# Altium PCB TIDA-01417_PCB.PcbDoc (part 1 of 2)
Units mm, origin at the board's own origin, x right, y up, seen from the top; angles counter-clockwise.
Board outline 64 x 64 mm, 2 copper layers (Top Layer, Bottom Layer), stack 1.575 mm thick; 69 components, 44 nets, 174 pads, 84 vias.
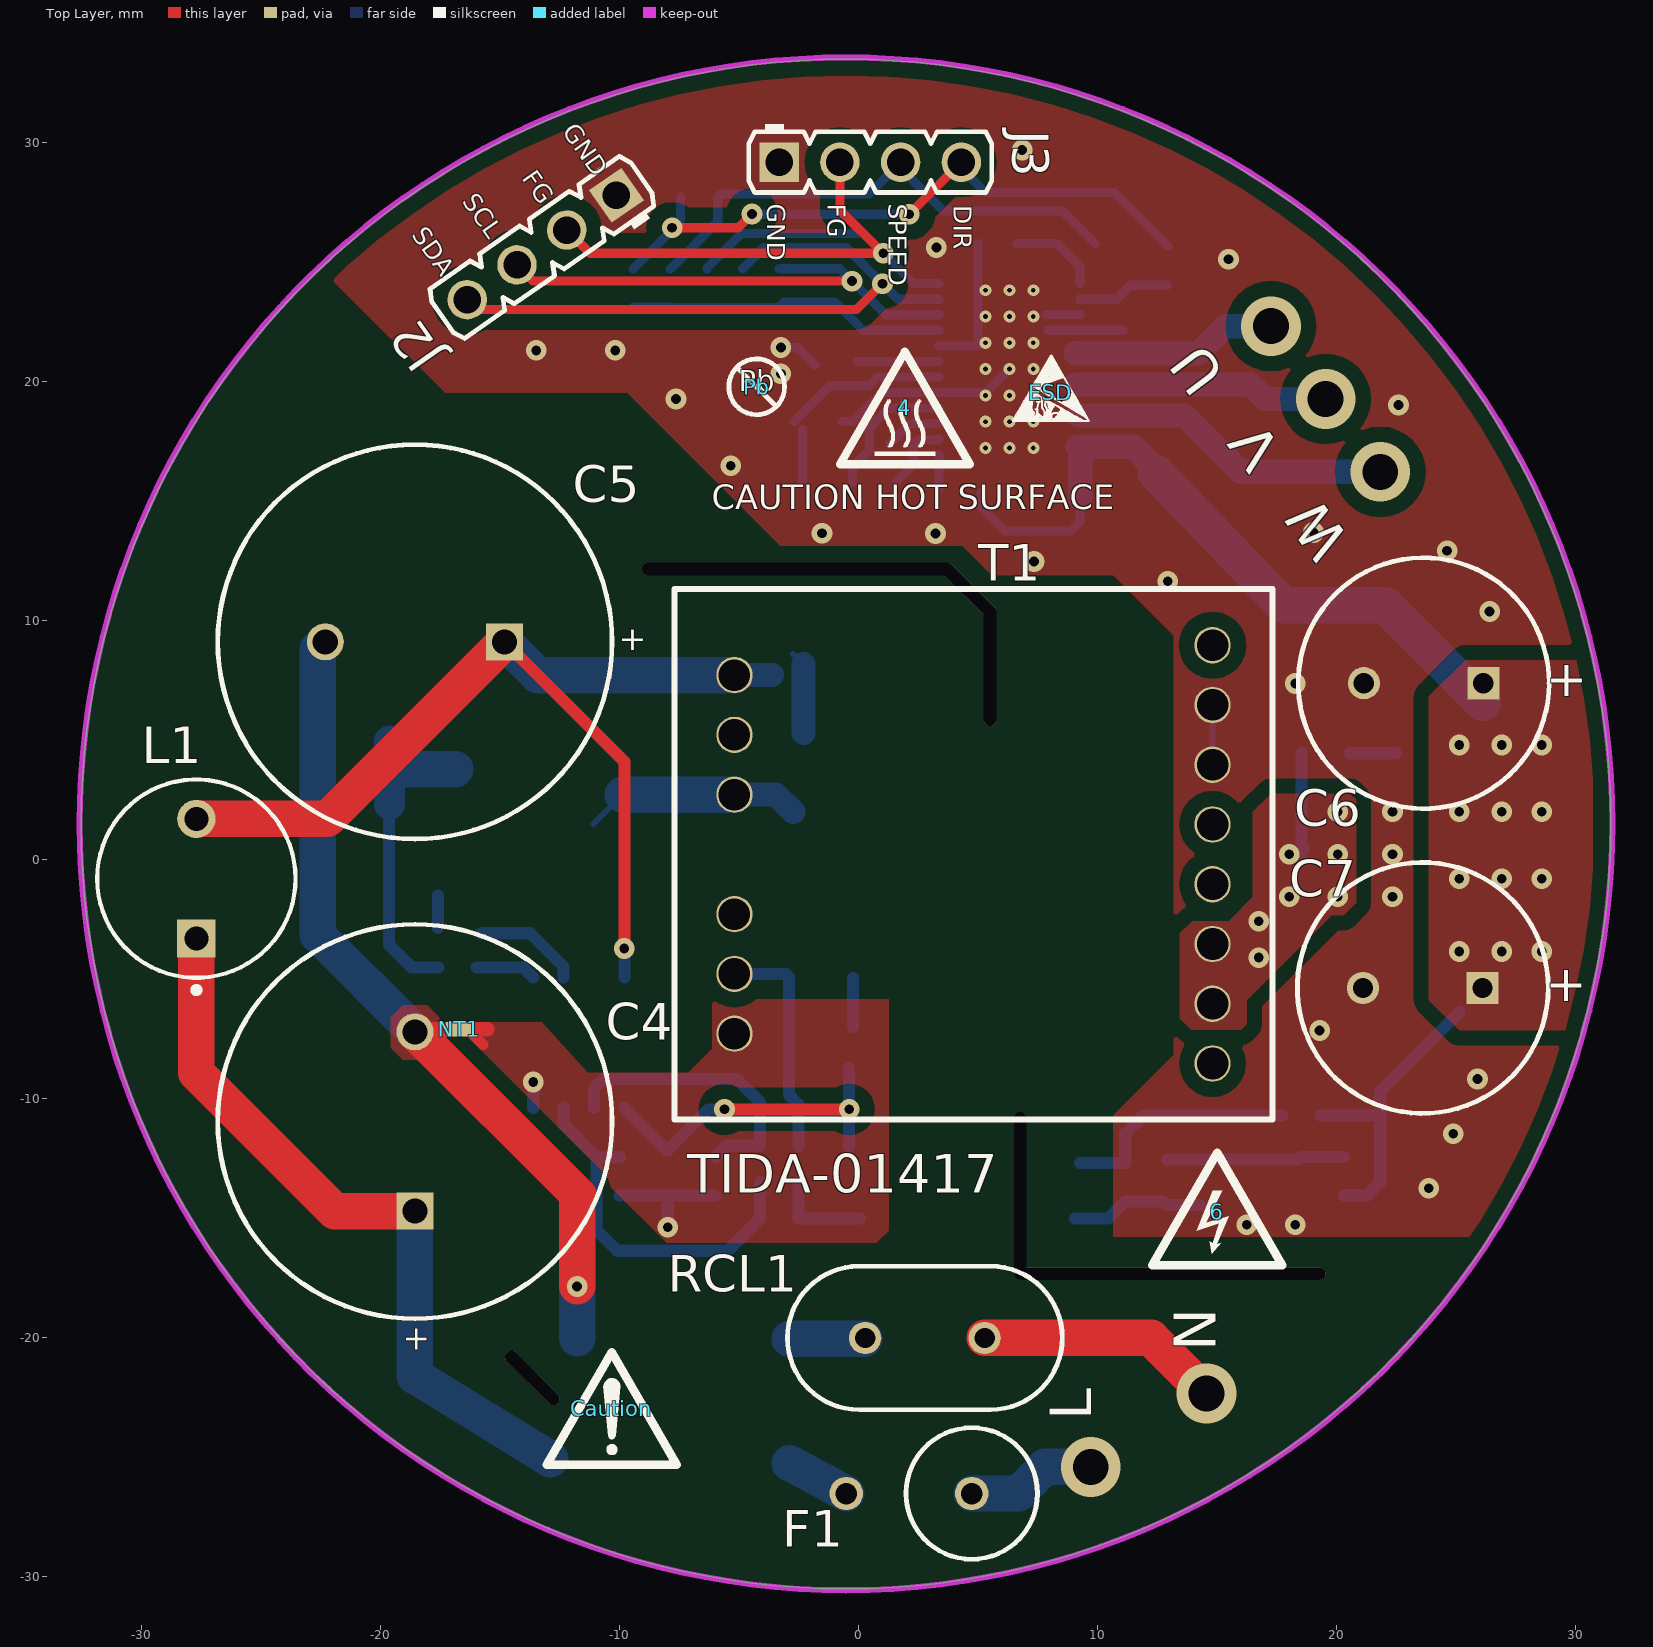
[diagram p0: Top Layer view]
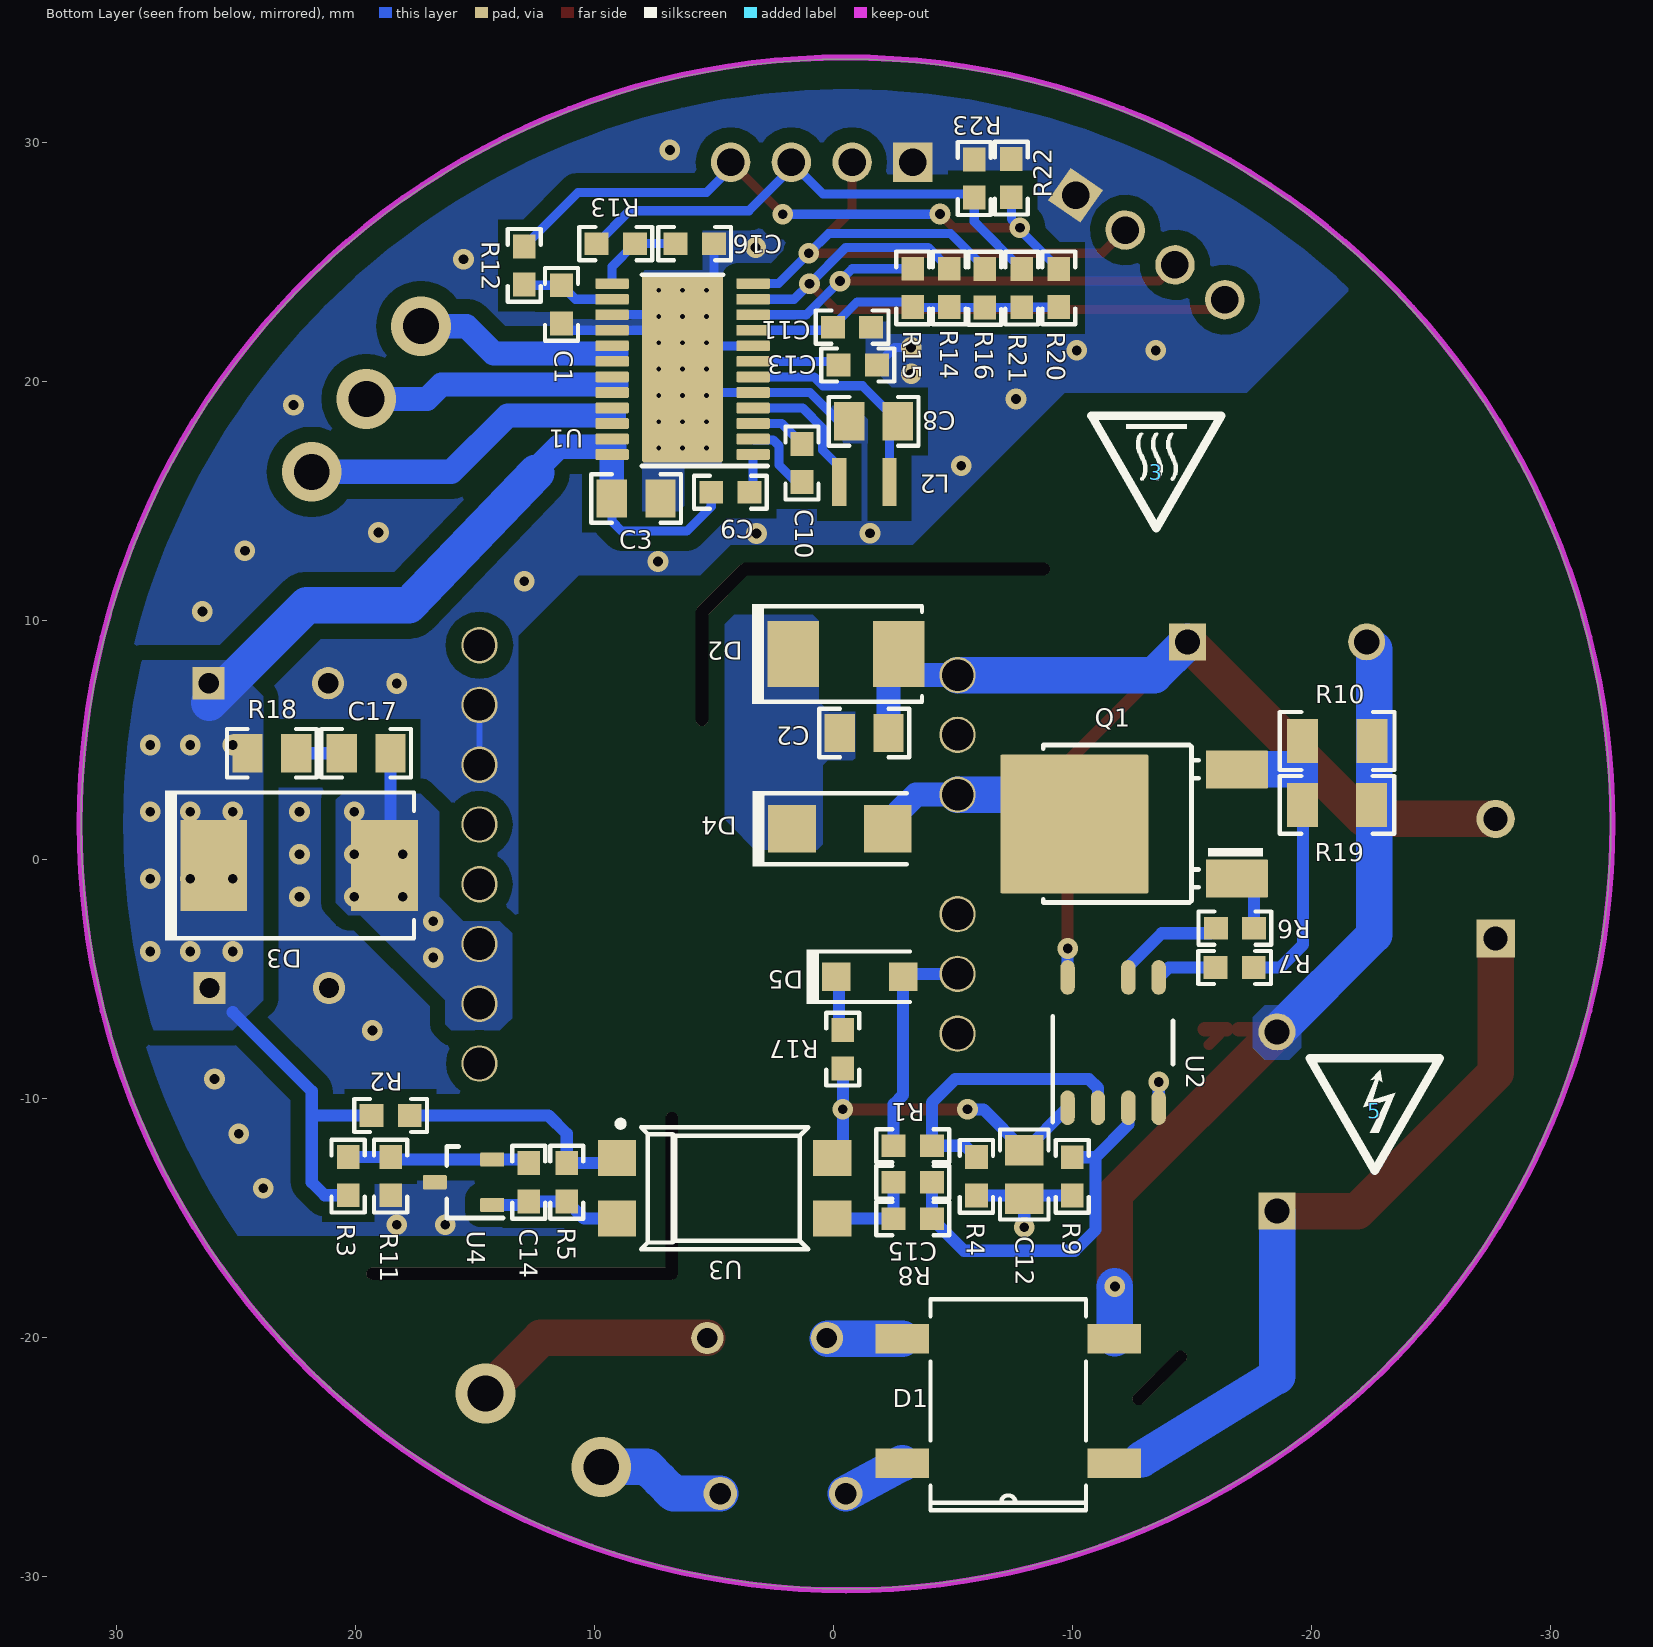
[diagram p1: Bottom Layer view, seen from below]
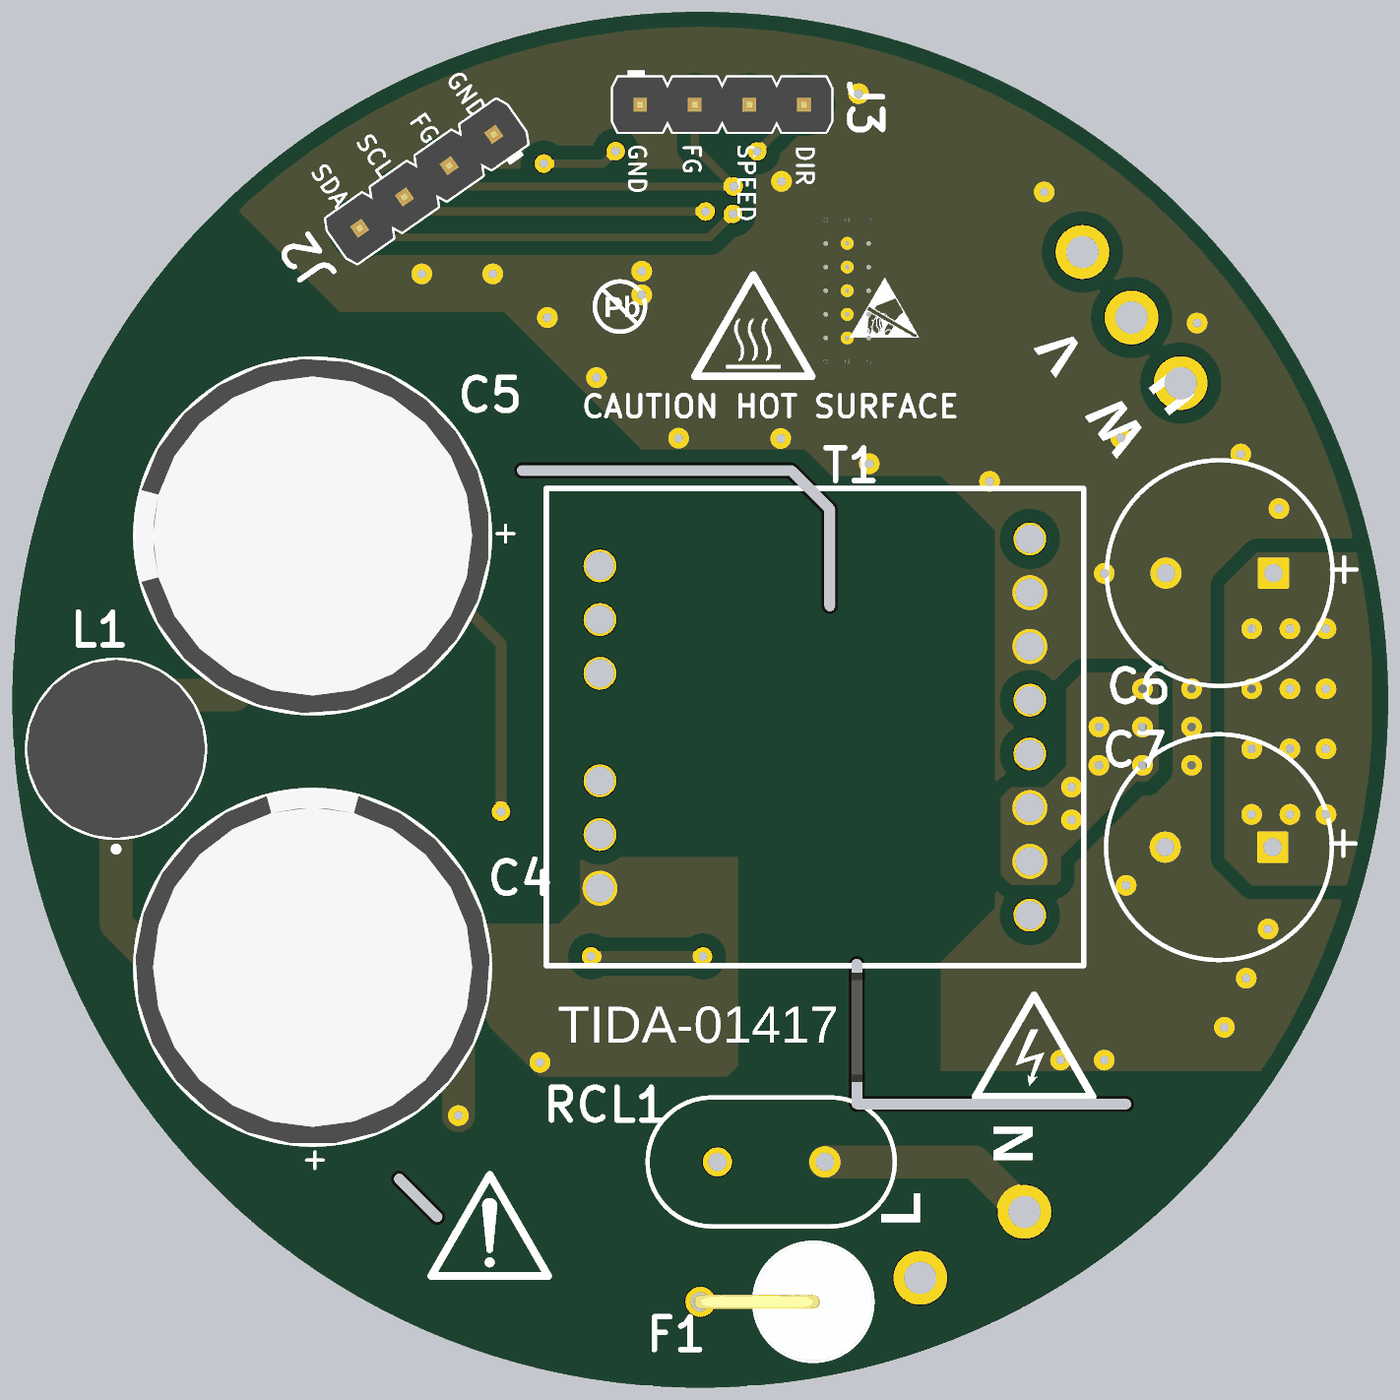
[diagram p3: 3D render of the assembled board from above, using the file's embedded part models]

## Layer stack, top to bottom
Top Solder: solder mask 0.0102, Solder Resist, Dk 3.5
Top Layer: signal copper 0.0356
Dielectric1: core 1.5037, FR-4, Dk 4.8
Bottom Layer: signal copper 0.0356
Bottom Solder: solder mask 0.0102, Solder Resist, Dk 3.5

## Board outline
-0.508,-30.514 cw(c-0.508,1.486) -32.508,1.486 cw(c-0.508,1.486) -0.508,33.486 cw(c-0.508,1.486) 31.492,1.486 cw(c-0.508,1.486)

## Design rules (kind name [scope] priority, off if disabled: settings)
AcuteAngle [All] p1: minimum=4.50000000000000E+0001 checktracksonly=FALSE
AssemblyTestPointUsage [All] p1: valid=2
BoardOutlineClearance BoardOutlineClearance_MountingHoles [OnCopper and InComponentClass('Mounting Holes')] p1: gap=1.016
BoardOutlineClearance BoardOutlineClearance_Poly [OnCopper and IsPoly] p2: gap=0.635
BoardOutlineClearance [OnCopper and Not InComponentClass('Logo') and not InComponentClass('FiducialMark') and not InRegion(1000,500,4000,800) and not InPoly] p3: gap=1.905
Clearance Clearance_Keepouts [((IsTrack Or IsArc) And Not InPoly) And IsFree and IsKeepOut vs ((IsTrack Or IsArc) And Not InPoly) And IsFree and IsKeepOut] p1: gap=0
Clearance Clearance_Poly [InPolygon] p2: gap=0.635
Clearance [All] p3: gap=0.2
ComponentClearance ComponentClearance_MountingHoles_FiducialMarks [InComponentClass('Mounting Holes') vs InComponentClass('FiducialMark')] p1: gap=1.27 collisioncheckmode=3 verticalgap=0.254 showdistances=FALSE
ComponentClearance ComponentClearance_Shunt [InComponentClass('Header') vs InComponentClass('Shunt')] p2: gap=0 collisioncheckmode=3 verticalgap=0 showdistances=FALSE
ComponentClearance ComponentClearance_Logo [InComponentClass('Logo')] p3: gap=1.27 collisioncheckmode=3 verticalgap=0.254 showdistances=FALSE
ComponentClearance ComponentClearance_ScrewToNut [(HasFootprint('NY PMS 440 0025 PH')) vs (HasFootprint('Keystone_1902C'))] p4: gap=0.127 collisioncheckmode=3 verticalgap=0.254 showdistances=FALSE
ComponentClearance ComponentClearance_MountingHoles [InComponentClass('Mounting Holes')] p5: gap=6.35 collisioncheckmode=3 verticalgap=2540 showdistances=FALSE
ComponentClearance ComponentClearance_SmallPassives [HasFootprint('0201*') or HasFootprint('0402*') or HasFootprint('0508') or HasFootprint('0603*') or HasFootprint('0612') or HasFootprint('0805*') or HasFootprint('0815*') or HasFootprint('0830*') or HasFootprint('1206*') or HasFootprint('1210*') or HasFootprint('1808*') or HasFootprint('1812*') or HasFootprint('1825*') or HasFootprint('2010*') or HasFootprint('2220*') or HasFootprint('2225*') or HasFootprint('2512*') or HasFootprint('2728*') or HasFootprint('3518*') vs HasFootprint('0201*') or HasFootprint('0402*') or HasFootprint('0508') or HasFootprint('0603*') or HasFootprint('0612') or HasFootprint('0805*') or HasFootprint('0815*') or HasFootprint('0830*') or HasFootprint('1206*') or HasFootprint('1210*') or HasFootprint('1808*') or HasFootprint('1812*') or HasFootprint('1825*') or HasFootprint('2010*') or HasFootprint('2220*') or HasFootprint('2225*') or HasFootprint('2512*') or HasFootprint('2728*') or HasFootprint('3518*')] p6: gap=0.38 collisioncheckmode=3 verticalgap=0.254 showdistances=FALSE
ComponentClearance ComponentClearance_THtoSMT [IsThruComponent vs IsSMTComponent] p7: gap=1.016 collisioncheckmode=3 verticalgap=0.762 showdistances=FALSE
ComponentClearance ComponentClearance_THtoTH [IsThruComponent vs IsThruComponent] p8: gap=0.762 collisioncheckmode=3 verticalgap=0.762 showdistances=FALSE
ComponentClearance [All] p9: gap=0.762 collisioncheckmode=3 verticalgap=0.254 showdistances=FALSE
DiffPairsRouting [All] p1: maxlimit=2.54 minlimit=0.254 mostfreqgap=0.254 toplayer_minwidth=0.381 toplayer_maxwidth=0.381 toplayer_prefwidth=0.381 bottomlayer_minwidth=0.381 bottomlayer_maxwidth=0.381 bottomlayer_prefwidth=0.381 maxuncoupledlength=25.4
FabricationTestPointUsage TestPointUsage [All] p1: valid=2 allowmultiple=FALSE
FabricationTestpoint Testpoint [All] p1: side=3 testpointundercomponent=TRUE minsize=1.016 maxsize=2.54 preferedsize=1.524 minholesize=0 maxholesize=1.016 preferedholesize=0.813 testpointgrid=0.025 allowsidetop=TRUE allowsidebottom=TRUE usegrid=TRUE gridtolerance=0
FanoutControl Fanout_LCC [IsLCC] p1: bgadir=Out bgaviamode=Centered fanoutstyle=Auto fanoutdirection=Alternating viagrid=0.025 // Fanout_LCC (Default Rule)
FanoutControl Fanout_BGA [IsBGA] p2: bgadir=Out bgaviamode=Centered fanoutstyle=Auto fanoutdirection=Alternating viagrid=0.025 // Fanout_BGA (Default Rule)
FanoutControl Fanout_Default [All] p4: bgadir=Out bgaviamode=Centered fanoutstyle=Auto fanoutdirection=Alternating viagrid=0.025 // Fanout_Default (Default Rule)
FanoutControl Fanout_Small [(CompPinCount < 5)] p5: bgadir=Out bgaviamode=Centered fanoutstyle=Auto fanoutdirection=OutThenIn viagrid=0.025 // Fanout_Small (Default Rule)
HoleSize [All] p1: absolutevalues=TRUE maxlimit=6.375 minlimit=0.2 maxpercent=80.000 minpercent=20.000
MinimumAnnularRing MinimumAnnularRing_ThermalPadVias [IsVia and InAnyComponent] p1: minimumring=0.15
MinimumAnnularRing [All] p2: minimumring=0.203
MinimumSolderMaskSliver MinimumSolderMaskSliver_Logo [InComponentClass('Logo') vs InComponentClass('Logo')] p1: minsoldermaskwidth=0.018
MinimumSolderMaskSliver [All] p2: minsoldermaskwidth=0.1
PlaneConnect [All] p1: planeconnectstyle=Relief reliefexpansion=0.254 reliefentries=4 reliefconductorwidth=0.254 reliefairgap=0.254
PolygonConnect [All] p1: connectstyle=Direct reliefconductorwidth=0.254 reliefentries=4 polygonreliefangle="90 Angle" airgapwidth=0.254
RoutingVias ThermalPadVias [IsVia and InAnyComponent] p1: holewidth=0.2 width=0.5 viastyle="Through Hole" minholewidth=0.2 minwidth=0.5 maxholewidth=0.33 maxwidth=0.6
RoutingVias [All] p2: holewidth=0.406 width=0.864 viastyle="Through Hole" minholewidth=0.2 minwidth=0.66 maxholewidth=1.016 maxwidth=1.651
SilkToBoardRegionClearance [Not ((IsComment or IsDesignator) And (Hide <> 'False')) and not InRegion(1000,500,4000,800)] p1:
SilkToSilkClearance SilkToSilkClearance_Pb-FreeLogo [(HasFootprint('Pb-Free_Overlay_Medium') OR HasFootprint('Pb-Free_Overlay_Small')) vs (HasFootprint('Pb-Free_Overlay_Medium') OR HasFootprint('Pb-Free_Overlay_Small'))] p1: silktosilkclearance=0
SilkToSilkClearance [All] p2: silktosilkclearance=0.102
SilkToSolderMaskClearance SilkToComponentPadClearance [IsPad and InAnycomponent] p1: minsilkscreentomaskgap=0.127 clearancetoexposedcopper=TRUE
SilkToSolderMaskClearance "Silk to Solder Mask Opening" [All] p2: minsilkscreentomaskgap=0.102 clearancetoexposedcopper=FALSE
SolderMaskExpansion [All] p1: expansion=0.05
Width [All] p1: maxlimit=2.54 minlimit=0.152 preferedwidth=0.254 checkconnectedcopper=TRUE
15 further rules are at their usual default settings.

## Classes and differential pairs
component class Header: J2 J3
component class AssemblyNote: ZZ1 ZZ2 ZZ3 ZZ4
component class TIDA-01417_BlankSheet: C1 C2 C3 C4 C5 C6 C7 C8 C9 C10 C11 C12 C13 C14 C15 C16 C17 D1 D2 D3 D4 D5 F1 J2 J3 L1 L2 NT1 Q1 R1 R2 R3 R4 R5 R6 R7 R8 R9 R10 R11 R12 R13 R14 R15 R16 R17 R18 R19 R20 R21 R22 R23 RCL1 T1 U1 U2 U3 U4
component class TIDA-01417_EVM_Hardware: 3 4 5 6 !PCB Caution ESD Pb ZZ1 ZZ2 ZZ3 ZZ4

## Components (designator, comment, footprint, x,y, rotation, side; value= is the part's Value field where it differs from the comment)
3 "CAUTION HOT SURFACE" IEC_HotSurface_small -13.496,16.2 r0 bottom
4 "CAUTION HOT SURFACE" IEC_HotSurface_small 1.96,18.896 r0 top
5 "HIGH VOLTAGE" IEC_HighVoltage_small -22.627,-10.539 r0 bottom
6 "HIGH VOLTAGE" IEC_HighVoltage_small 15.022,-14.742 r0 top
C1 "CGA3E2X7R2A102K080AA" 0603 11.394,23.225 r90 bottom
C2 "C0805C102JBRACTU" 0805_HV#1 -1.27,5.296 r0 bottom
C3 "C2012X5R1V106K085AC" 0805_HV#1 8.271,15.106 r0 bottom
C4 "ESMG451ELL470MLP1S" SMG_1600x3550 -18.542,-10.96 r90 top
C5 "ESMG451ELL470MLP1S" SMG_1600x3550 -18.542,9.106 r180 top
C6 "ELXZ350ELL471MJ20S" Chemi-Con_1000x2000 23.658,7.377 r180 top
C7 "ELXZ350ELL471MJ20S" Chemi-Con_1000x2000 23.622,-5.372 r180 top
C8 "C2012X5R1V106K085AC" 0805_HV#1 -1.663,18.331 r180 bottom
C9 "C1608X5R1H104K080AA" 0603 4.328,15.363 r0 bottom
C10 "C1608X5R1H104K080AA" 0603 1.333,16.587 r90 bottom
C11 "C1608X5R1H105K080AB" 0603 -0.762,22.273 r0 bottom
C12 "C2012X5R1V106K085AC" 0805_HV#1 -7.965,-13.176 r90 bottom
C13 "C1608X5R1H105K080AB" 0603 -1,20.685 r0 bottom
C14 "GRM188R71H561KA01D" 0603 12.764,-13.5 r270 bottom
C15 "C1608X5R1H473K080AA" 0603 -3.302,-13.5 r0 bottom
C16 "CGA3E2X7R2A102K080AA" 0603 5.821,25.765 r0 bottom
C17 "C0805C102JBRACTU" 0805_HV#1 19.565,4.445 r0 bottom
Caution "CAUTION.  READ USER GUIDE BEFORE USE" IEC_Caution_small -10.303,-22.96 r0 top
D1 "DF1506S-T" DF-S -7.296,-22.652 r0 bottom
D2 "SMBJ170A-13-F" SMB -0.508,8.598 r180 bottom
D3 "MBRS4201T3G" SMC 22.37,-0.248 r180 bottom
D4 "US1M-13-F" SMA -0.254,1.284 r180 bottom
D5 "PMEG10010ELRX" SOD-123W -1.505,-4.904 r180 bottom
ESD "ESD Susceptible" ESD_Overlay_small 8.045,19.556 r0 top
F1 "048712.5MXEP" Fuse_217_015_Verical 4.752,-26.523 r0 top
J2 "61300411121" WURTH_61300411121#1 -13.208,25.87 r225 top
J3 "61300411121" WURTH_61300411121#2 0.508,29.172 r0 top
L1 "768772102" WE-TI_8095 -27.686,-0.8 r90 top
L2 "CB2518T470K" IND_CB2518 -1.28,15.789 r180 bottom
NT1 "Net-Tie" Net-Tie_10mil -16.681,-7.104 r180 top net-tie
Pb "Pb-Free Symbol" Pb-Free_Overlay_Small -4.244,19.777 r0 top
Q1 "SPD04N80C3" DPAK -13.462,1.486 r0 bottom
R1 "RC0603FR-0775KL" 0603 -3.302,-11.976 r0 bottom
R2 "RC0603FR-071K5L" 0603 18.542,-10.706 r0 bottom
R3 "RT0603BRD07383KL" 0603 20.32,-13.246 r270 bottom
R4 "RC0603JR-0724KL" 0603 -5.964,-13.253 r90 bottom
R5 "RC0603FR-071KL" 0603 11.176,-13.5 r90 bottom
R6 "MCR03EZPJ000" 0603 -16.78,-2.872 r180 bottom
R7 "RC0603JR-072K7L" 0603 -16.765,-4.515 r180 bottom
R8 "RC0603FR-07100KL" 0603 -3.302,-15.024 r180 bottom
R9 "RC0603FR-0722KL" 0603 -9.974,-13.254 r90 bottom
R10 "ERJ-8RQFR43V" 1206 -21.056,4.957 r0 bottom
R11 "RC0603FR-0744K2L" 0603 18.542,-13.246 r90 bottom
R12 "RC0603FR-07100RL" 0603 12.954,24.854 r270 bottom
R13 "RC0603FR-07100RL" 0603 9.123,25.765 r180 bottom
R14 "RC0603JR-075K1L" 0603 -4.826,23.914 r90 bottom
R15 "RC0603JR-075K1L" 0603 -3.302,23.914 r90 bottom
R16 "RC0603JR-075K1L" 0603 -6.317,23.898 r90 bottom
R17 "CRCW060310R0JNEA" 0603 -0.375,-7.935 r90 bottom
R18 "RC0805JR-0710RL" 0805_HV#2 23.513,4.447 r180 bottom
R19 "NC" 1206 -21.049,2.284 r0 bottom
R20 "RC0603JR-075K1L" 0603 -9.406,23.912 r270 bottom
R21 "RC0603JR-075K1L" 0603 -7.863,23.902 r270 bottom
R22 "RC0603JR-075K1L" 0603 -7.424,28.505 r270 bottom
R23 "RC0603JR-075K1L" 0603 -5.875,28.49 r270 bottom
RCL1 "B57236S479M" THERM_B57236S0 2.792,-20.016 r180 top
T1 "Used in BOM report" PCBComponent_1 4.826,0.216 r0 top
U1 "DRV10983PWP" PWP0024B_N 6.329,20.515 r0 bottom
U2 "UCC28740DR" D0007A_N -11.684,-7.658 r90 bottom
U3 "LTV-817S" DIP254P762X350-4 4.572,-13.754 r180 bottom
U4 "TL431BQDBZT" DBZ0003A_N 15.494,-13.5 r0 bottom
ZZ1 "This Assembly Note is for PCB labels only" AssemblyNoteLabel -45.593,61.125 r0 top
ZZ2 "These assemblies are ESD sensitive, ESD precautions shall be observed." AssemblyNote -45.593,58.359 r0 top
ZZ3 "These assemblies must be clean and free from flux and all contaminants. Use of no clean flux is not acceptable." AssemblyNote -45.593,56.11 r0 top
ZZ4 "These assemblies must comply with workmanship standards IPC-A-610 Class 2, unless otherwise specified." AssemblyNote -45.593,53.861 r0 top

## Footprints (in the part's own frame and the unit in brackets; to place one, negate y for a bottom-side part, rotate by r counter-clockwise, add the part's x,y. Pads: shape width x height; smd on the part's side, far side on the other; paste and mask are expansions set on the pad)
0603 [mm] "0603 from SM-752 data"
  rect 1x0.95 smd: 1(-0.8,0) 2(0.8,0)
  silkscreen extent -1.52,-0.69 1.52,0.69, body extent -0.87,-0.47 0.87,0.47, height 1
0805_HV#1 [mil] "0805 with 30mil clearance between pads"
  rect 50x63 smd: 1(-40,0) 2(40,0)
  silkscreen extent -74,-40 74,40, body extent -43,-29 43,29, height 57
0805_HV#2 [mil] "0805 with 30mil clearance between pads"
  rect 50x63 smd: 1(40,0) 2(-40,0)
  silkscreen extent -74,-40 74,40, body extent -43,-29 43,29, height 57
1206 [mm] "1206 from SM-752 data"
  rect 1.3x1.85 smd: 1(-1.45,0) 2(1.45,0)
  silkscreen extent -2.4,-1.21 2.4,1.21, body extent -1.7,-0.9 1.7,0.9, height 1.35
AssemblyNote [mm] "Assembly Note"
AssemblyNoteLabel [mm] "Assembly Note for PCB Labels"
Chemi-Con_1000x2000 [mm] "TH, 2-Leads, Body 10x20mm, Pin Spacing 5mm"
  rect 1.35x1.35 hole 0.85: 1(-2.5,0)
  round 1.35 hole 0.85: 2(2.5,0)
  silkscreen extent -5.25,-5.25 5.25,5.25, body extent -5.25,-5.25 5.25,5.25, height 21.5
D0007A_N [mm] "SOIC, 7-Leads, Body 4.9x3.9mm, Pitch 1.27mm, IPC Medium Density"
  oval 1.45x0.6 smd: 1(-2.725,1.905) 2(-2.725,0.635) 3(-2.725,-0.635) 4(-2.725,-1.905) 5(2.725,-1.905) 6(2.725,-0.635) 8(2.725,1.905)
  silkscreen extent -3.32,-2.5 1.1,2.52, body extent -3.01,-2.45 3.01,2.45, height 1.75
DBZ0003A_N [mm] "SOT23, 3-Leads, Body 2.9x1.3mm, Pitch 0.95mm, Lead Span 2.4mm, IPC Medium Density"
  rrect17% 1x0.6 smd: 1(-1.2,0.95) 2(-1.2,-0.95) 3(1.2,0)
  silkscreen extent -1.65,-1.5 0.7,1.5, body extent -1.26,-1.46 1.26,1.46, height 0.98
DF-S [mil] "Diodes Inc. recommended land pattern per ap02001.pdf rev 30"
  rect 88x49 smd: 1(-174.5,102.36) 2(-174.5,-102.36) 3(174.5,-102.36) 4(174.5,102.36)
  silkscreen extent -128,-168 128,180, body extent -205,-168 205,168, height 108
DIP254P762X350-4 [mm] "LITE-ON"
  rect 1.6x1.5 smd: 1(-4.5,1.27) 2(-4.5,-1.27) 3(4.5,-1.27) 4(4.5,1.27)
  silkscreen extent -4.47,-2.55 3.5,2.82, body extent -5.23,-2.55 5.23,2.55, height 4.62
DPAK [mm] "D-PAK, 3-Pads, Body 6.22x6.73mm (max), TO-252AA using nominal STEP model"
  rrect6% 2.6x1.6 smd: 1(-3.4,2.28) 3(-3.4,-2.28)
  rrect2% 6.2x5.8 smd paste-2.9: 4(3.4,0)
  silkscreen extent -4.5,-3.3 4.7,3.28, body extent -3.86,-3.29 5.84,3.29, height 2.48
ESD_Overlay_small [mm]
  silkscreen extent -1.58,-1.23 1.62,1.55
Fuse_217_015_Verical [mm] "TH, 2-Leads, Dia 5.5mm, Vertical, Pin Spacing 5.25mm"
  round 1.4 hole 0.9: 1(0,0) 2(-5.25,0)
  silkscreen extent -2.75,-2.75 2.75,2.75, body extent -5.57,-2.74 2.75,2.75, height 23.82
IEC_Caution_small [mm]
  silkscreen extent -2.72,-2.36 2.72,2.35
IEC_HighVoltage_small [mm]
  silkscreen extent -2.72,-2.24 2.72,2.47
IEC_HotSurface_small [mm]
  silkscreen extent -2.72,-2.36 2.72,2.35
IND_CB2518 [mm] "TAIYO YUDEN"
  rect 0.6x2 smd: 1(-1.05,0) 2(1.05,0)
  body extent -1.35,-1 1.35,1, height 2
Net-Tie_10mil [mm] "10mil net tie, no solder mask opening, no solder paste"
  rect 0.6x0.6 smd paste-0.127 mask-0.127: 1(-0.254,0) 2(0.254,0)
  Top Layer region: -0.152,0.127 0.152,0.127 0.152,-0.127 -0.152,-0.127
Pb-Free_Overlay_Small [mm]
  silkscreen extent -1.16,-1.17 1.17,1.17
PCBComponent_1 [mm]
  round 1.524 hole 1.32: 1(-10,7.5) 2(-10,5) 3(-10,2.5) 4(-10,-2.5) 5(-10,-5) 6(-10,-7.5) 7(10,-8.75) 8(10,-6.25) 9(10,-3.75) 10(10,-1.25) 11(10,1.25) 12(10,3.75) 13(10,6.25) 14(10,8.75)
  silkscreen extent -12.5,-11.1 12.5,11.1
PWP0024B_N [mm] "TSOP, 24-Leads, Body 7.9x4.5mm (max), Pitch 0.65mm, IPC Medium Density"
  rrect22% 1.4x0.45 smd: 1(-2.95,3.575) 2(-2.95,2.925) 3(-2.95,2.275) 4(-2.95,1.625) 5(-2.95,0.975) 6(-2.95,0.325) 7(-2.95,-0.325) 8(-2.95,-0.975) 9(-2.95,-1.625) 10(-2.95,-2.275) 11(-2.95,-2.925) 12(-2.95,-3.575) 13(2.95,-3.575) 14(2.95,-2.925) 15(2.95,-2.275) 16(2.95,-1.625) 17(2.95,-0.975) 18(2.95,-0.325) 19(2.95,0.325) 20(2.95,0.975) 21(2.95,1.625) 22(2.95,2.275) 23(2.95,2.925) 24(2.95,3.575)
  rrect6% 3.4x7.8 smd paste-2 mask-2: 25(0,0)
  rrect4% 2.4x5.16 on Bottom Paste: 25(0,0)
  rrect4% 2.4x5.16 on Bottom Solder: 25(0,0)
  silkscreen extent -3.55,-3.95 1.7,4.05, body extent -3.21,-3.9 3.21,3.9, height 1.2
SMA [mm] "Molded Diode, 2-Leads, Body 4.3x2.6mm, IPC Medium Density, based on OnSemi component dimensions and land pattern"
  rect 2x2 smd: 1(-2,0) 2(2,0)
  silkscreen extent -3.66,-1.57 2.79,1.57, body extent -2.6,-1.3 2.6,1.3, height 2.42
SMB [mm] "Molded Diode, 2-Leads, Body 5.4x3.6mm, IPC Medium Density, based on OnSemi component dimensions"
  rect 2.159x2.743 smd: 1(-2.21,0) 2(2.21,0)
  silkscreen extent -3.94,-2.08 3.18,2.08, body extent -2.7,-1.8 2.7,1.8, height 2.32
SMC [mil] "Molded Diode, 2-Leads, Body 6.9x5.8mm, IPC Medium Density, based on OnSemi component dimensions and land patterns"
  rect 110x150 smd: 1(-140.49,0) 2(140.49,0)
  silkscreen extent -221,-123 189,124, body extent -156,-116 157,116, height 91
SMG_1600x3550 [mm] "TH, 2-Leads, Dia 16mm, Pin Spacing 7.5mm"
  rect 1.55x1.55 hole 1.05: 1(-3.75,0)
  round 1.55 hole 1.05: 2(3.75,0)
  silkscreen extent -8.25,-8.25 8.25,8.25, body extent -8.25,-8.25 8.26,8.25, height 37.01
SOD-123W [mm] "NXP recommended land pattern"
  rect 1.2x1.2 smd paste-0.05: 1(-1.4,0) 2(1.4,0)
  silkscreen extent -2.64,-1.14 1.68,1.14, body extent -1.85,-0.95 1.85,0.95, height 1.1
THERM_B57236S0 [mm] "EPCOS"
  round 1.35 hole 0.85: 1(-2.5,0) 2(2.5,0)
  silkscreen extent -5.75,-3 5.75,3, body extent -5.75,-3 5.7,3, height 15.99
WE-TI_8095 [mm] "Wurth WE-TI 8095"
  rect 1.6x1.6 hole 1: 1(-2.5,0)
  round 1.6 hole 1: 2(2.5,0)
  silkscreen extent -4.79,-4.15 4.15,4.15, body extent -4.12,-4.14 4.15,4.14, height 10
WURTH_61300411121#1 [mm] "Header, 2.54mm, 4x1, TH"
  rect 1.65x1.65 hole 1.15 rot 170: 1(-3.549,0.832)
  round 1.65 hole 1.15: 2(-1.047,0.391) 3(1.454,-0.05) 4(3.956,-0.491)
  silkscreen extent -4.93,-1.92 5.34,2.51, body extent -5.02,-1.96 5.43,2.3, height 8.54
WURTH_61300411121#2 [mm] "Header, 2.54mm, 4x1, TH"
  rect 1.65x1.65 hole 1.15: 1(-3.81,0)
  round 1.65 hole 1.15: 2(-1.27,0) 3(1.27,0) 4(3.81,0)
  silkscreen extent -5.08,-1.27 5.08,1.6, body extent -5.08,-1.27 5.08,1.27, height 8.54

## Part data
3 4: library part IEC_HotSurface, "IEC 61010-1 Hot Surface Warning"
5 6: library part IEC_HighVoltage, "IEC 61010-1 High Voltage Warning"
C1 C16: "CAP, CERM, 1000 pF, 100 V, +/- 10%, X7R, AEC-Q200 Grade 1, 0603"
C2 C17: "CAP, CERM, 1000 pF, 630 V, +/- 5%, X7R, 0805"
C3 C8 C12: "CAP, CERM, 10 µF, 35 V, +/- 10%, X5R, 0805"
C4 C5: "CAP, AL, 47 µF, 450 V, +/- 20%, TH"
C6 C7: "CAP, AL, 470 µF, 35 V, +/- 20%, AEC-Q200 Grade 2, TH"
C9 C10: "CAP, CERM, 0.1 µF, 50 V, +/- 10%, X5R, 0603"
C11 C13: "CAP, CERM, 1 µF, 50 V, +/- 10%, X5R, 0603"
C14: "CAP, CERM, 560 pF, 50 V, +/- 10%, X7R, 0603"
C15: "CAP, CERM, 0.047 µF, 50 V, +/- 10%, X5R, 0603"
Caution: library part IEC_Caution, "IEC 61010-1 Caution Warning"
D1: "Diode, Switching-Bridge, 600 V, 1.5 A, DF-S"
D2: "Diode, TVS, Uni, 170 V, 275 Vc, SMB"
D3: "Diode, Schottky, 200 V, 4 A, SMC"
D4: "Diode, Ultrafast, 1000 V, 1 A, SMA"
D5: "Diode, Schottky, 100 V, 1 A, AEC-Q101, SOD-123W"
ESD: library part ESD_Susceptible, "ESD Susceptible Symbol"
F1: library part 0217015.MXEP, "FUSE 420VAC/DC 5X20 FA PT 12.5A"
J2 J3: "Header, 2.54 mm, 4x1, Gold, TH"
L1: "Inductor, Shielded Drum Core, Metal Composite, 1 mH, 0.5 A, 1.7 ohm, TH"
L2: "Inductor, Wirewound, Ferrite, 47 µH, 0.11 A, 1.235 ohm, SMD"
NT1: "Single point connection between nets."
Pb: library part Pb-Free
Q1: "MOSFET, N-CH, 800 V, 4 A, DPAK"
R1: "RES, 75.0 k, 1%, 0.1 W, 0603"
R2: "RES, 1.50 k, 1%, 0.1 W, 0603"
R3: "RES, 383 k, 0.1%, 0.1 W, 0603"
R4: "RES, 24 k, 5%, 0.1 W, 0603"
R5: "RES, 1.00 k, 1%, 0.1 W, 0603"
R6: "RES, 0, 5%, 0.1 W, 0603"
R7: "RES, 2.7 k, 5%, 0.1 W, 0603"
R8: "RES, 100 k, 1%, 0.1 W, 0603"
R9: "RES, 22.0 k, 1%, 0.1 W, 0603"
R10: "RES, 0.43, 1%, 0.25 W, AEC-Q200 Grade 1, 1206"
R11: "RES, 44.2 k, 1%, 0.1 W, 0603"
R12 R13: "RES, 100, 1%, 0.1 W, 0603"
R14 R15 R16 R20 R21 R22 R23: "RES, 5.1 k, 5%, 0.1 W, 0603"
R17: "RES, 10, 5%, 0.1 W, 0603"
R18: "RES, 10, 5%, 0.125 W, 0805"
R19: library part ERJ-8RQFR82V, "RES, 0.82, 1%, 0.25 W, 1206"
RCL1: library part B57236S0100M000, "ICL 4.7 OHM 20% 4.6A 11.51MM"
T1: library part 36W24V
U1: "12- to 24-V, Three-Phase, Sensorless BLDC Motor Driver, PWP0024B (TSSOP-24)"
U2: "Constant-Voltage, Constant-Current Flyback Controller Using Opto-Coupler Feedback, D0007A (SOIC-7)"
U3: "Optocoupler, 5 kV, 50-600% CTR, SMT"
U4: "Adjustable Precision Shunt Regulator, 34 ppm / degC, 100 mA, -40 to 125 degC, 3-pin SOT-23 (DBZ), Green (RoHS & no Sb/Br)"
ZZ1: library part AssemblyNoteLabel
ZZ2 ZZ3 ZZ4: library part AssemblyNote

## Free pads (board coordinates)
  oval 0.508x3 hole 0.508 slot 3 at 135 deg unplated rot 45 mask+0.127: 0(-13.629,-21.686) 0(4.615,11.258)
  oval 13x0.508 hole 0.508 slot 13 at 0 deg unplated mask+0.127: 0(-2.54,12.154) 0(13.05,-17.324)
  oval 0.508x5 hole 0.508 slot 5 at 90 deg unplated mask+0.127: 0(5.516,8.097)
  oval 0.508x7 hole 0.508 slot 7 at 90 deg unplated mask+0.127: 0(6.777,-14.062)

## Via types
v1: diameter 0.864, hole 0.406, Top Layer to Bottom Layer, 58 vias
v2: diameter 0.5, hole 0.2, Top Layer to Bottom Layer, 15 vias
v3: diameter 0.5, hole 0.2, Top Layer to Bottom Layer, tented both sides, 6 vias
v4: diameter 2.5, hole 1.5, Top Layer to Bottom Layer, 5 vias

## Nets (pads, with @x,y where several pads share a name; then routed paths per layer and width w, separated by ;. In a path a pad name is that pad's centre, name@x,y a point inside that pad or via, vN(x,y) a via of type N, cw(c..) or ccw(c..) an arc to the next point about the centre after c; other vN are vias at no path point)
+3.3V: C11.2 R14.1 R15.1 R16.1 R20.2 R21.2 U1.9 | length 13
  Bottom Layer w0.381: R20.2@-9.397,23.102 R21.2@-7.863,23.102 -7.859,23.098 R16.1@-6.317,23.098 R15.1@-3.318,23.098 ; R15.1@-3.237,23.179 -3.086,23.33 -0.978,23.33 C11.2@0.038,22.314 ; C11.2@0.211,22.14 U1.9@3.38,22.14
+24V: C3.2 C6.1 C7.1 C9.2 D3.1 R2.2 R3.2 R18.2 U1.23 U1.24 | length 42.6
  Bottom Layer w0.381: C9.2@5.128,15.363 5.128,14.763 6.153,13.738 8.867,13.738 9.28,14.151 C3.2@9.28,15.098
  Bottom Layer w0.508: R2.2@19.342,-10.706 21.844,-10.706 ; R3.2@20.32,-14.046 21.298,-14.046 21.844,-13.5 21.844,-10.706 ; 25.146,-6.388 21.844,-9.69 21.844,-10.706
  Bottom Layer w1.016: 9.175,17.265 11.512,17.265 12.445,16.332 12.445,16.187 ; C3.2@9.287,15.106 U1.24@9.287,17.154
  Bottom Layer w1.524: 12.445,16.187 17.78,10.63 22.058,10.63 26.122,6.566
  other v1: 25.146,-3.848 26.924,-3.848 28.602,-3.848 25.146,-0.8 26.924,-0.8 28.602,-0.8 25.146,1.994 26.924,1.994 28.602,1.994 25.146,4.788 26.924,4.788 28.602,4.788
DIR: J3.4 R12.1 R20.1 R22.2 | length 27
  Top Layer w0.381: v1(-7.783,26.43) -5.017,26.43 v1(-4.439,27.008) ; v1(2.14,26.994) J3.4@4.318,29.172
  Bottom Layer w0.381: R20.1@-9.406,24.712 v1@-7.736,26.383 ; v1(-7.783,26.43) -7.424,26.79 R22.2@-7.424,27.705 ; v1(-4.439,27.008) -4.439,26.994 v1(2.14,26.994) ; J3.4@4.318,28.918 5.334,27.902 10.706,27.902 R12.1@12.954,25.654
FG: J2.2 J3.2 R16.2 U1.12 | length 29.4
  Top Layer w0.381: J2.2@-12.191,26.334 -11.219,25.362 v1(1.048,25.362) -0.762,27.172 J3.2@-0.762,29.172
  Bottom Layer w0.381: R16.2@-6.317,24.698 -6.317,24.751 -4.882,26.186 0.224,26.186 v1(1.048,25.362) 2.32,24.09 U1.12@3.38,24.09
GND: C1.1 C3.1 C6.2 C7.2 C8.1 C11.1 C13.1 C16.1 J2.1 J3.1 R11.1 R22.1 R23.1 T1.12 T1.13 U1.5 U1.8 U1.15 U1.16 U1.25@6.329,20.515 U4.3 | length 22.3
  Bottom Layer w0.254: T1.12@14.826,3.966 T1.13@14.826,6.466
  Bottom Layer w0.381: v1@-3.205,21.421 -2.536,21.421 -2.341,21.226 C13.1@-1.8,20.685 ; C8.1@-0.647,18.331 -0.205,18.331 1.004,19.54 U1.5@3.38,19.54 5.355,19.54 v2(6.329,20.515) ; U1.8@3.38,21.49 U1.25@5.021,21.49 ; U1.25@5.021,21.823 C16.1@5.021,25.765 ; U1.25@7.853,22.801 U1.15@9.28,22.79 ; U1.25@7.955,22.14 U1.16@9.28,22.14 C1.1@11.109,22.14
  other v1: 16.256,-15.278 18.288,-15.278 23.876,-13.754 24.892,-11.468 25.908,-9.182 19.304,-7.15 22.352,-1.562 22.352,0.216 22.352,1.994 18.288,7.366 26.416,10.376 12.954,11.646 7.356,12.467 24.638,12.916 3.234,13.639 -1.515,13.653 19.05,13.678 -5.334,16.472 22.606,19.012 -7.62,19.266 -3.232,20.325 -13.462,21.298 -10.16,21.298 -3.232,21.421 15.494,25.108 3.274,25.602 6.858,29.68
  other v2: 5.329,18.315 6.329,18.315 7.33,18.315 5.329,19.415 6.329,19.415 7.33,19.415 5.329,20.515 7.33,20.515 5.329,21.615 6.329,21.615 7.33,21.615 5.329,22.715 6.329,22.715 7.33,22.715
  other v3: 5.329,17.215 6.329,17.215 7.33,17.215 5.329,23.815 6.329,23.815 7.33,23.815
L: F1.1 | length 5.4
  Bottom Layer w1.524: F1.1@4.752,-26.523 6.709,-26.523 7.283,-25.949 7.823,-25.409 v4(9.731,-25.409)
N: RCL1.1 | length 10.2
  Top Layer w1.524: RCL1.1@5.292,-20.016 12.254,-20.016 v4(14.576,-22.338)
NetC1_2: C1.2 R12.2 U1.14 | length 3.9
  Bottom Layer w0.381: U1.14@9.28,23.44 10.809,23.44 C1.2@11.394,24.025 R12.2@12.925,24.025
NetC2_2: C2.2 D2.1 D4.1
NetC4_1: C4.1 D1.1 L1.1 | length 30.7
  Top Layer w1.524: L1.1@-27.686,-3.3 -27.686,-8.928 -21.904,-14.71 C4.1@-18.542,-14.71
  Bottom Layer w1.524: C4.1@-18.542,-14.71 -18.542,-21.609 -12.874,-25.091
NetC8_2: C8.2 L2.2 U1.6 | length 9
  Bottom Layer w0.381: C8.2@-2.679,18.331 -1.19,19.82 0.462,19.82 0.832,20.19 U1.6@3.38,20.19 ; L2.2@-2.33,15.789 C8.2@-2.33,17.982
NetC9_1: C9.1 U1.1 | length 1.4
  Bottom Layer w0.381: C9.1@3.38,15.511 U1.1@3.38,16.94
NetC10_1: C10.1 U1.2 | length 3
  Bottom Layer w0.381: C10.1@1.576,15.787 2.289,16.5 2.289,17.298 2.547,17.556 3.345,17.556 U1.2@3.38,17.59
NetC10_2: C10.2 U1.3 | length 2.4
  Bottom Layer w0.381: C10.2@1.333,17.387 2.187,18.24 U1.3@3.38,18.24
NetC12_2: C12.2 R17.1 U2.1 U3.4 | length 14.3
  Top Layer w0.508: v1(-5.588,-10.452) v1(-0.378,-10.452)
  Bottom Layer w0.508: U2.1@-9.779,-10.383 -8.002,-12.16 C12.2@-7.965,-12.16 -6.257,-10.452 v1(-5.588,-10.452) v1@-5.657,-10.383 ; U3.4@-0.378,-12.034 v1(-0.378,-10.452) R17.1@-0.378,-8.717
NetC13_2: C13.2 U1.7 | length 3.4
  Bottom Layer w0.381: C13.2@-0.045,20.84 U1.7@3.38,20.84
NetC14_1: C14.1 R3.1 R11.2 U4.2 | length 7.4
  Bottom Layer w0.508: C14.1@12.914,-12.55 U4.2@14.294,-12.55 18.438,-12.55 R11.2@18.542,-12.446 R3.1@20.32,-12.446
NetC14_2: C14.2 R5.1 U3.2 U4.1 | length 5.4
  Bottom Layer w0.508: U3.2@9.072,-15.024 10.452,-15.024 R5.1@11.176,-14.3 C14.2@12.764,-14.3 ; C14.2@12.914,-14.45 U4.1@14.294,-14.45
NetC15_1: C15.1 R8.2 R9.2 U2.3 | length 15.9
  Bottom Layer w0.508: U2.3@-12.319,-10.383 -12.319,-11.087 -10.952,-12.454 ; R9.2@-9.974,-12.454 -10.952,-12.454 ; C15.1@-4.102,-13.5 R8.2@-4.102,-15.024 -5.442,-16.364 -10.077,-16.364 -10.952,-15.489 -10.952,-12.454
NetC15_2: C15.2 R8.1 U3.3 | length 4.1
  Bottom Layer w0.508: C15.2@-2.502,-13.5 R8.1@-2.502,-15.024 U3.3@0.072,-15.024
NetC16_2: C16.2 R13.2 U1.13 | length 3.8
  Bottom Layer w0.381: C16.2@6.621,25.765 R13.2@8.324,25.765 9.28,24.809 U1.13@9.28,24.09
NetC17_1: C17.1 D3.2 T1.8 T1.9 | length 4.5
  Bottom Layer w0.254: D3.2@18.784,0.423 D3.2@18.784,0.47
  Bottom Layer w0.508: D3.2@18.55,0.004 C17.1@18.55,4.445
  other v1: 16.764,-4.102 16.764,-2.578 18.034,-1.562 20.066,-1.562 18.041,0.224 20.066,0.216 20.066,1.994
NetC17_2: C17.2 R18.1 | length 1.9
  Bottom Layer w0.508: C17.2@20.582,4.445 R18.1@22.495,4.445
NetD1_3: D1.3 RCL1.2 | length 3.1
  Bottom Layer w1.524: D1.3@-2.864,-20.052 RCL1.2@0.256,-20.052
NetD1_4: D1.4 F1.2 | length 2.7
  Bottom Layer w1.524: D1.4@-2.864,-25.252 F1.2@-0.498,-26.523
NetD4_2: D4.2 Q1.4 T1.3 | length 9.2
  Bottom Layer w0.254: Q1.4@-11.078,1.486 Q1.4@-9.848,2.716
  Bottom Layer w1.016: T1.3@-5.174,2.716 -3.44,2.716 D4.2@-2.718,1.994
  Bottom Layer w1.524: Q1.4@-9.848,2.716 T1.3@-5.174,2.716
NetD5_1: D5.1 R17.2 | length 2
  Bottom Layer w0.508: R17.2@-0.212,-6.996 D5.1@-0.212,-4.963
